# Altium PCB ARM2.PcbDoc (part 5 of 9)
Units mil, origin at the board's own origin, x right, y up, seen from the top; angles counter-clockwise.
Board outline 4700.79 x 3937.01 mil, 6 copper layers (Top Layer, GND02, ART03, ART04, PWR05, Bottom Layer); 697 components, 508 nets, 2326 pads, 1231 vias.
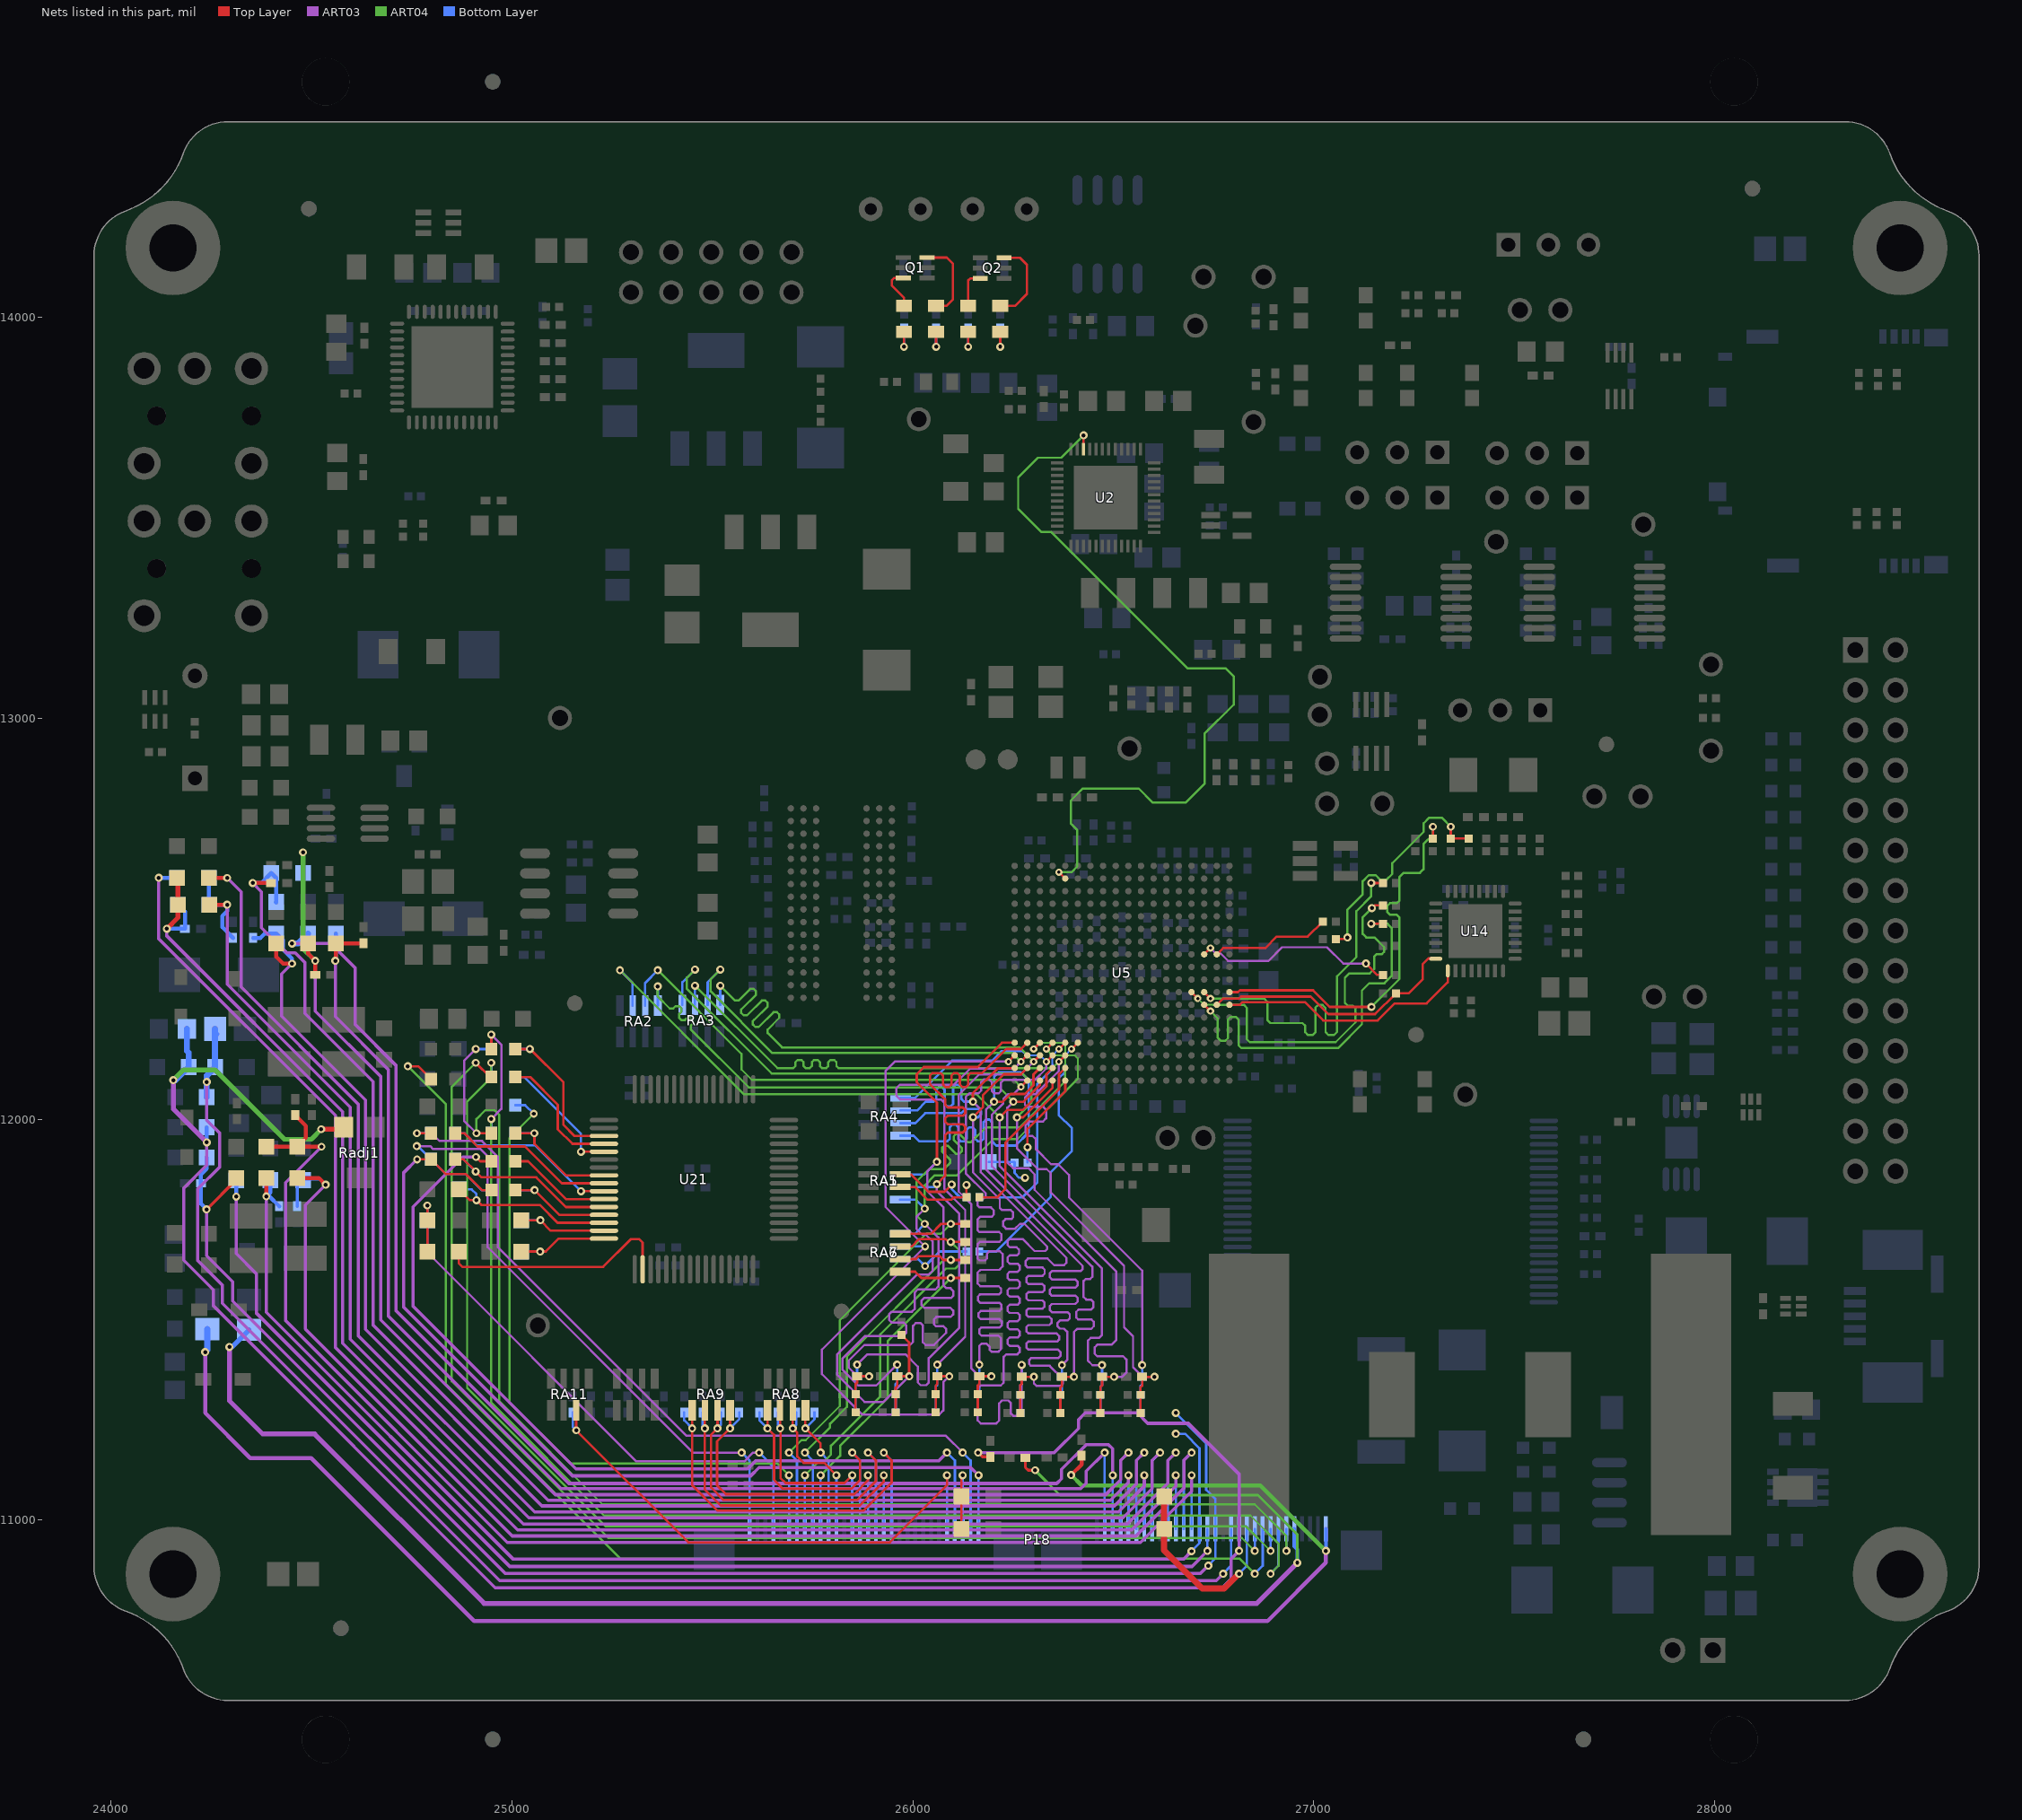
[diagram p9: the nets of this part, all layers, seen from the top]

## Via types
v1: diameter 20, hole 10, Top Layer to Bottom Layer, tented both sides, 871 vias
v2: diameter 18, hole 8, Top Layer to Bottom Layer, tented both sides, 273 vias
v3: diameter 22, hole 10, Top Layer to Bottom Layer, tented both sides, 64 vias
v4: diameter 20, hole 10, Top Layer to Bottom Layer, 18 vias
v5: diameter 22, hole 12, Top Layer to Bottom Layer, 4 vias
v6: diameter 39.37, hole 19.68, Top Layer to Bottom Layer, 1 vias

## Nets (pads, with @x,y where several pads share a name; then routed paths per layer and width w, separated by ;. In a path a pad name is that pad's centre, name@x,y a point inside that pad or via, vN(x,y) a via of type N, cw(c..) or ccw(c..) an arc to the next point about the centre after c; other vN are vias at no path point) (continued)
L_BO5: C240.1 P18.26 RA11.7 | length 1351.3
  Top Layer w6: RA11.7@25160.75,11269.25 v1(25160.75,11224.12) 25440.24,10944.62 25943,10944.62 26085.28,11086.9 v1(26085.28,11112.04)
  Bottom Layer w6: C240.1@25152.2,11268.62 25152.2,11232.66 v1(25160.75,11224.12) ; P18.26@26085.28,10978.27 v1(26085.28,11112.04)
L_CKHH: P18.4 R183.2 R187.1 R190.1 | length 1526
  Top Layer w6: R187.1@24789.63,11670 R183.2@24789.63,11748 v1(24789.63,11784.87)
  ART03 w5.5: v1(24789.63,11784.87) 24789.63,11667.99 25311,11146.62 25580,11146.62 25602,11168.62 v1(25617,11168.62)
  Bottom Layer w6: R190.1@24789.63,11748 v1(24789.63,11784.87) ; v1(25617,11168.62) 25652.21,11133.42 P18.4@25652.2,10978.27
L_CKV: R182.1 U21.5 | length 324.2
  Top Layer w6: v1(25172.64,11918.9) U21.5@25229.96,11918.9
  Bottom Layer w6: R182.1@25008.92,12105 25031,12105 25172.64,11963.36 v1(25172.64,11918.9)
L_CKVH: P18.55 R182.2 | length 3098.4
  ART04 w5.5: v1(24949.08,12140.63) 24949.08,12104.53 24888.8,12044.25 24888.8,11329.9 25234.12,10984.57 26831.03,10984.57 v1(26892.36,10923.24)
  Bottom Layer w6: R182.2@24949.08,12105 v1(24949.08,12140.63) ; v1(26892.36,10923.24) P18.55@26892.36,10978.27
L_CLK1: R187.2 U21.18 | length 590.3
  Top Layer w6: R187.2@24868.37,11670 24868.37,11640.23 24876.8,11631.8 25227.67,11631.8 25296.67,11700.8 25318.25,11700.8 25326.42,11692.63 U21.18@25326.42,11625.59
L_DIO1: P18.1 R148.2 R171.2 | length 1690.6
  ART03 w5.5: v1(24763,11933) 24796.62,11933 24804,11925.62 24922,11925.62 24940,11907.62 24940,11680.62 25451.94,11168.68 v1(25573.47,11168.68)
  Bottom Layer w6: v1(24763,11933) 24766.08,11933 R148.2@24799.08,11900 24836.08,11863 24885,11863 24925,11823 R171.2@24949.45,11823 ; v1(25573.47,11168.68) 25593.16,11148.99 P18.1@25593.16,10978.27
L_DIO2: P18.30 R166.2 R174.2 | length 2358.8
  Top Layer w6: v1(24764,11900) R166.2@24799.08,11900 24836.08,11863 24886,11863 24926,11823 R174.2@24949.45,11823
  ART03 w8: v1(24764,11900) 24730,11866 24730,11531.62 25151,11110.62 25596,11110.62 25617,11131.62 26144.43,11131.62 v1(26164.02,11112.04)
  Bottom Layer w6: P18.30@26164.02,10978.27 v1(26164.02,11112.04)
L_GO0: C226.1 P18.14 RA8.6 | length 537.1
  Top Layer w6: RA8.6@25669.25,11274.25 v1(25669.25,11229.12) 25670.21,11228.16 25670.21,11105.42 25683,11092.62 25829.64,11092.62 v1(25849.06,11112.04)
  Bottom Layer w6: C226.1@25663.47,11268.62 25663.47,11234.9 v1(25669.25,11229.12) ; P18.14@25849.06,10978.27 v1(25849.06,11112.04)
L_GO1: C227.1 P18.15 RA8.5 | length 735.9
  Top Layer w6: RA8.5@25637.76,11274.25 v1(25637.76,11229.12) 25654,11212.87 25654,11100.62 25676,11078.62 25846.75,11078.62 25868.75,11100.62 25868.75,11148.99 v1(25849.06,11168.68)
  Bottom Layer w6: C227.1@25617.71,11268.62 25617.71,11249.17 v1(25637.76,11229.12) ; v1(25849.06,11168.68) 25868.75,11148.99 P18.15@25868.74,10978.27
L_GO2: C228.1 P18.16 RA9.8 | length 796.4
  Top Layer w6: RA9.8@25544.49,11274.25 v1(25544.49,11229.12) 25512.12,11196.76 25512.12,11086.57 25534.08,11064.62 25854,11064.62 25888.43,11099.05 v1(25888.43,11112.04)
  Bottom Layer w6: v1(25544.49,11229.12) 25567.24,11251.87 C228.1@25567.24,11268.62 ; P18.16@25888.43,10978.27 v1(25888.43,11112.04)
L_GO3: C229.1 P18.17 RA9.7 | length 963.3
  Top Layer w6: RA9.7@25512.99,11274.25 v1(25512.99,11229.12) 25497.12,11213.25 25497.12,11081.57 25528.08,11050.62 25861,11050.62 25908.12,11097.74 25908.12,11148.99 v1(25888.43,11168.68)
  Bottom Layer w6: v1(25512.99,11229.12) 25521.48,11237.61 C229.1@25521.48,11268.62 ; v1(25888.43,11168.68) 25908.12,11148.99 P18.17@25908.11,10978.27
L_GO4: C233.1 P18.18 RA9.6 | length 876.8
  Top Layer w6: RA9.6@25481.5,11274.25 v1(25481.5,11229.12) 25481.5,11076.2 25521.08,11036.62 25868,11036.62 25927.8,11096.42 v1(25927.8,11112.04)
  Bottom Layer w6: C233.1@25475.71,11268.62 25475.71,11234.9 v1(25481.5,11229.12) ; P18.18@25927.8,10978.27 v1(25927.8,11112.04)
L_GO5: C234.1 P18.19 RA9.5 | length 1069.5
  Top Layer w6: RA9.5@25450,11274.25 v1(25450,11229.12) 25450,11086.7 25513.08,11023.62 25877,11023.62 25947.49,11094.11 25947.49,11148.99 v1(25927.8,11168.68)
  Bottom Layer w6: C234.1@25429.95,11268.62 25429.95,11249.17 v1(25450,11229.12) ; v1(25927.8,11168.68) 25947.49,11148.99 P18.19@25947.48,10978.27
L_LDH: P18.27 R177.2 | length 2213.9
  Top Layer w6: v1(24911,11905.62) 24921.62,11895 R177.2@24949.08,11895
  ART03 w8: v1(24911,11905.62) 24878,11905.62 24754,11781.62 24754,11533.62 25160,11127.62 25588,11127.62 25608,11147.62 26064.22,11147.62 v1(26085.28,11168.68)
  Bottom Layer w6: v1(26085.28,11168.68) 26104.97,11148.99 P18.27@26104.96,10978.27
L_OE: R180.1 U21.4 | length 325.7
  Top Layer w6: R180.1@25008.92,12105 25046,12105 25115,12036 25115,11975 25151.42,11938.58 U21.4@25229.96,11938.58
L_OEH: P18.53 R180.2 | length 3105.3
  Top Layer w6: v1(24910.45,12140.63) 24946.08,12105 R180.2@24949.08,12105
  ART04 w5.5: v1(24910.45,12140.63) 24850.62,12080.8 24850.62,11346.08 25241.12,10955.57 26820.66,10955.57 v1(26852.99,10923.24)
  Bottom Layer w6: v1(26852.99,10923.24) P18.53@26852.99,10978.27
L_POL: R188.1 U21.10 | length 430.9
  Top Layer w6: v1(25172.64,11820.47) U21.10@25229.96,11820.47
  Bottom Layer w6: R188.1@24858.92,11965 24882,11965 24912,11935 25058.11,11935 v1(25172.64,11820.47)
L_POLH: P18.29 R185.2 R188.2 | length 2092.7
  Top Layer w6: v1(24763.45,11965) R185.2@24799.08,11965
  ART03 w5.5: v1(24763.45,11965) 24800.62,11965 24820,11945.62 24926,11945.62 24965,11906.62 24965,11681.62 25436.05,11210.57 26082.75,11210.57 v1(26124.65,11168.68)
  Bottom Layer w6: v1(24763.45,11965) R188.2@24799.08,11965 ; v1(26124.65,11168.68) 26144.34,11148.99 P18.29@26144.33,10978.27
L_REV: P18.28 R146.2 R169.1 | length 268.8
  Top Layer w6: R146.2@26121.65,10978.27 R169.1@26121.65,11059.16 26121.65,11109.04 v1(26124.65,11112.04)
  Bottom Layer w6: P18.28@26124.65,10978.27 v1(26124.65,11112.04)
L_RLB: P18.6 R197.2 | length 1706.6
  ART04 w5.5: v1(25055,12013.62) 24994.12,11952.75 24994.12,11293.57 25146.12,11141.57 25662.04,11141.57 v1(25691.58,11112.04)
  Bottom Layer w6: R197.2@25008.92,12035 25033.62,12035 v1(25055,12013.62) ; P18.6@25691.58,10978.27 v1(25691.58,11112.04)
L_RO0: C220.1 P18.7 RA7.8 | length 1136.5
  Top Layer w6: RA7.8@25968.37,11714.24 26046.24,11714.24 26071,11739 v1(26095,11739) C220.1@26131,11739
  ART04 w5.5: v1(25691.58,11168.68) 25722.52,11199.62 25733,11199.62 25818,11284.62 25818,11498.62 26033.62,11714.24 26070.24,11714.24 v1(26095,11739)
  Bottom Layer w6: v1(25691.58,11168.68) 25711.27,11148.99 P18.7@25711.26,10978.27
L_RO1: C221.1 P18.8 RA7.7 | length 1080
  Top Layer w6: RA7.7@25968.37,11682.75 25997.75,11682.75 26016,11701 26082,11701 26089,11694 v1(26095,11694) C221.1@26131,11694
  ART04 w5.5: v1(25730.95,11112.04) 25765.53,11146.62 25779,11146.62 25796,11163.62 25796,11185.62 25919,11308.62 25919,11463.62 26083,11627.62 26106,11627.62 26118,11639.62 26118,11671 v1(26095,11694)
  Bottom Layer w6: P18.8@25730.95,10978.27 v1(25730.95,11112.04)
L_RO2: C222.1 P18.9 RA7.6 | length 1009.7
  Top Layer w6: RA7.6@25968.37,11651.25 26008.25,11651.25 26015.62,11658.62 26066.87,11658.62 26076.5,11649 v1(26095,11649) C222.1@26131,11649
  ART04 w5.5: v1(25730.95,11168.68) 25794,11231.73 25794,11240.62 25836,11282.62 25836,11407.62 26077.38,11649 v1(26095,11649)
  Bottom Layer w6: v1(25730.95,11168.68) 25750.64,11148.99 P18.9@25750.63,10978.27
L_RO3: C223.1 P18.10 RA7.5 | length 929.4
  Top Layer w6: RA7.5@25968.37,11619.76 26006,11619.76 26021.76,11604 v1(26095,11604) C223.1@26131,11604
  ART04 w5.5: v1(25770.32,11112.04) 25819,11160.72 25819,11185.62 25938,11304.62 25938,11447 v1(26095,11604)
  Bottom Layer w6: P18.10@25770.32,10978.27 v1(25770.32,11112.04)
L_RO4: C224.1 P18.11 RA8.8 | length 368.8
  Top Layer w6: RA8.8@25732.24,11274.25 v1(25732.24,11229.12) 25770.32,11191.05 v1(25770.32,11168.68)
  Bottom Layer w6: v1(25732.24,11229.12) 25755,11251.87 C224.1@25755,11268.62 ; v1(25770.32,11168.68) 25790.01,11148.99 P18.11@25790,10978.27
L_RO5: C225.1 P18.12 RA8.7 | length 414.1
  Top Layer w6: RA8.7@25700.75,11274.25 v1(25700.75,11229.12) 25712,11217.87 25712,11158.62 25728,11142.62 25779.1,11142.62 v1(25809.69,11112.04)
  Bottom Layer w6: v1(25700.75,11229.12) 25709.24,11237.61 C225.1@25709.24,11268.62 ; P18.12@25809.69,10978.27 v1(25809.69,11112.04)
L_SEL0: R204.2 R208.1 U21.16 | length 267.6
  Top Layer w6: R204.2@25023.37,11670 v1(25071,11670) 25085,11670 25117.36,11702.36 U21.16@25229.96,11702.36
  Bottom Layer w6: R208.1@25023.37,11670 v1(25071,11670)
L_SEL1: R205.2 R209.1 U21.15 | length 264.6
  Top Layer w6: R205.2@25023.74,11748 v1(25071.37,11748) 25097.32,11722.05 U21.15@25229.96,11722.05
  Bottom Layer w6: R209.1@25023.74,11748 v1(25071.37,11748)
L_SEL2: R206.2 R210.1 U21.14 | length 459.7
  Top Layer w6: R206.2@24868.37,11825 24895.37,11798 v1(24912,11798) 24924,11786 25070,11786 25114.27,11741.73 U21.14@25229.96,11741.73
  Bottom Layer w6: R210.1@24868.37,11825 24900,11825 24912,11813 v1(24912,11798)
L_SPOL: R185.1 U21.9 | length 422.7
  Top Layer w6: R185.1@24858.92,11965 24882,11965 24915,11932 25033,11932 25124.84,11840.16 U21.9@25229.96,11840.16
L_STB: R177.1 U21.11 | length 260.1
  Top Layer w6: R177.1@25008.92,11895 25041,11895 25135.21,11800.79 U21.11@25229.96,11800.79
L_STH1: R148.1 R166.1 U21.12 | length 484.1
  Top Layer w6: R166.1@24858.92,11900 24880,11900 v1@24910,11870 ; v1@24909.81,11869.81 v1(24910,11869.62) 24924.62,11855 25061,11855 25134.9,11781.1 U21.12@25229.96,11781.1
  Bottom Layer w6: R148.1@24858.92,11900 24879.62,11900 v1(24910,11869.62)
L_STH2: R171.1 R174.1 U21.13 | length 291.9
  Top Layer w6: R174.1@25009.29,11823 v1@25055,11823 ; v1(25056.92,11823) 25118.5,11761.42 U21.13@25229.96,11761.42
  Bottom Layer w6: R171.1@25009.29,11823 v1(25056.92,11823)
L_STV1: R179.1 R181.1 U21.8 | length 327.8
  Top Layer w6: R181.1@25008.92,11965 v1(25056.55,11965) 25056.55,11938.45 25135.16,11859.84 U21.8@25229.96,11859.84
  Bottom Layer w6: R179.1@25008.92,11965 v1(25056.55,11965)
L_STV2: R184.1 R186.1 U21.3 | length 409
  Top Layer w6: R184.1@25008.92,12175 v1(25045,12175) 25046,12175 25129,12092 25129,11986 25156.73,11958.27 U21.3@25229.96,11958.27
  Bottom Layer w6: R186.1@25008.92,12175 v1(25045,12175)
L_STVDH: P18.57 R181.2 R186.2 | length 3325.6
  Top Layer w6: v1(24912,11965) R181.2@24949.08,11965
  ART03 w5.5: v1(24910.45,12175) 24881,12145.55 24881,11996 v1(24912,11965)
  ART04 w5.5: v1(24912,11965) 24912,12000.45 24934.12,12022.57 24957.12,12022.57 24969.12,12010.57 24969.12,11296.57 25226.2,11039.5 26852.81,11039.5 26931.73,10960.57 v1(26931.73,10923.24)
  Bottom Layer w6: v1(24910.45,12175) R186.2@24949.08,12175 ; v1(26931.73,10923.24) P18.57@26931.73,10978.27
L_STVUH: P18.56 R179.2 R184.2 | length 3321.9
  Top Layer w6: R184.2@24949.08,12175 v1(24949.08,12210.92)
  ART03 w5.5: v1(24949.08,12000.63) 24974,12025.55 24974,12186 v1(24949.08,12210.92)
  ART04 w5.5: v1(24949.08,12000.63) 24949.08,11292.62 25230.12,11011.57 26842.12,11011.57 26912.05,10941.65 26912.05,10886.29 v1(26892.36,10866.6)
  Bottom Layer w6: R179.2@24949.08,11965 v1(24949.08,12000.63) ; v1(26892.36,10866.6) 26912.05,10886.29 P18.56@26912.05,10978.27
L_UDB: P18.54 R196.2 | length 3236.3
  Top Layer w6: v1(24741,12132) 24767.08,12132 R196.2@24799.08,12100
  ART04 w5.5: v1(24741,12132) 24835.12,12037.88 24835.12,11339.57 25270.12,10904.57 26815.01,10904.57 v1(26852.99,10866.6)
  Bottom Layer w6: v1(26852.99,10866.6) 26872.68,10886.29 P18.54@26872.68,10978.27
L_V1: C264.1 P18.34 R224.2 R225.1 | length 3331.9
  Top Layer w10: v1(24560,12395) 24561,12396 R225.1@24561,12438 24629,12438 C264.1@24630,12439
  ART03 w8: v1(24560,12395) 24560,12255.7 24692,12123.7 24692,11509.62 25123,11078.62 26419,11078.62 26432.61,11092.24 26432.61,11122.01 v1@26478.97,11168.37
  Bottom Layer w6: v1(26478.66,11168.68) 26478.66,10978.58 P18.34@26478.98,10978.27
  Bottom Layer w10: v1(24560,12395) 24561,12396 R224.2@24561,12463
L_V2: P18.35 R218.2 | length 3353.7
  ART03 w8: v1(24451.91,12438) 24548.7,12438 24609.12,12377.57 24609.12,12236.57 24711,12134.7 24711,11522.62 25142,11091.62 26359,11091.62 26371,11103.62 26371,11126.62 26433,11188.62 26488,11188.62 26498.66,11177.96 v1(26498.66,11112.04)
  Bottom Layer w6: P18.35@26498.66,10978.27 v1(26498.66,11112.04)
  Bottom Layer w15: v1(24451.91,12438) 24466.91,12438 R218.2@24491.91,12463
L_V3: C266.1 P18.36 R226.2 R227.1 | length 3699
  Top Layer w10: R226.2@24491.91,12438 24491.91,12413.09 v1(24510,12395) C266.1@24510,12360
  ART03 w8: v1(24510,12395) 24510,12269.7 24673,12106.7 24673,11499.62 25109,11063.62 26481,11063.62 26518.34,11100.96 26518.34,11148.99 v1(26538.03,11168.68)
  ART04 w12: v1(24479.37,12665.52) 24479.37,12425.63 v1(24510,12395)
  Bottom Layer w6: P18.36@26518.35,10978.27 26518.34,11148.99 v1(26538.03,11168.68)
  Bottom Layer w10: R227.1@24479.37,12614 v1(24479.37,12665.52)
L_V4: C267.1 P18.37 R227.2 R228.1 | length 3655.2
  Top Layer w10: v1(24354.11,12589) C267.1@24400,12589
  ART03 w8: v1(24354.11,12589) 24376.06,12567.06 24376.06,12477.69 24438.74,12415 24460,12415 24484.12,12390.88 24484.12,12263.57 24654,12093.7 24654,11486.62 25091,11049.62 26493,11049.62 26538.03,11094.65 v1(26538.03,11112.04)
  Bottom Layer w6: P18.37@26538.03,10978.27 v1(26538.03,11112.04)
  Bottom Layer w10: v1(24354.11,12589) 24375.63,12589 R227.2@24400.63,12614 24412.81,12601.81 R228.1@24412.81,12541.74 ; R228.1@24411.94,12540.87 R228.1@24412.81,12540
L_V5: C268.1 P18.38 R228.2 R229.1 | length 3654.9
  Top Layer w10: R229.1@24412.81,12438 24412.81,12405.18 24430,12388 v1(24451.91,12388)
  ART03 w7: 24426.12,12362.22 v1(24451.91,12388)
  ART03 w8: 24426.12,12362.22 24426.12,12256.88 24635,12048 24635,11475.62 25075,11035.62 26503,11035.62 26557.71,11090.33 26557.71,11148.99 v1(26577.4,11168.68)
  Bottom Layer w6: P18.38@26557.72,10978.27 26557.71,11148.99 v1(26577.4,11168.68)
  Bottom Layer w10: C268.1@24355,12452 24373,12452 24384,12463 R228.2@24412.81,12463 24429.06,12446.75 24429.06,12423.61 24451.91,12400.77 v1(24451.91,12388)
L_V6: P18.39 R221.2 | length 3652.3
  Top Layer w6: v1@24290.06,12602 v1(24290.33,12601.72)
  Top Layer w10: R221.2@24244.72,12602 v1@24290.06,12602
  ART03 w8: v1(24290.33,12601.72) 24325.07,12566.99 24325.07,12329.93 24617,12038 24617,11460.62 25057,11020.62 26513,11020.62 26577.4,11085.02 v1(26577.4,11112.04)
  Bottom Layer w6: P18.39@26577.4,10978.27 v1(26577.4,11112.04)
L_V7: C270.1 P18.40 R222.1 R230.2 R231.1 | length 3978.1
  Top Layer w10: R231.1@24246.3,12535 v1(24290.33,12535)
  ART03 w8: v1(24290.33,12535) 24290.33,12336.36 24597,12029.7 24597,11451.62 25043,11005.62 26524,11005.62 26597.08,11078.7 26597.08,11148.99 v1(26616.77,11168.68)
  Bottom Layer w6: P18.40@26597.09,10978.27 26597.08,11148.99 v1(26616.77,11168.68)
  Bottom Layer w10: R230.2@24244.72,12602 24244.72,12535 R222.1@24246.3,12535 v1(24290.33,12535) 24290.33,12519.33 24278,12507 24278,12479 C270.1@24305,12452
L_V8: C271.1 P18.42 R222.2 R231.2 R232.1 | length 4037.7
  Top Layer w6: R232.1@24166.26,12601.37 R232.1@24165.63,12602 R232.1@24167.56,12600.07
  Top Layer w12: v1(24140,12475) 24167.56,12502.56 R231.2@24167.56,12535 R232.1@24167.56,12600.07
  ART03 w8: v1(24140,12475) 24140,12456.7 24578,12018.7 24578,11441.62 25029,10990.62 26535,10990.62 26636.45,11092.07 26636.45,11148.99 v1(26656.14,11168.68)
  Bottom Layer w6: P18.42@26636.46,10978.27 26636.45,11148.99 v1(26656.14,11168.68)
  Bottom Layer w10: v1(24140,12475) C271.1@24185,12475 24185,12517.56 R222.2@24167.56,12535
L_V9: P18.43 R219.2 | length 3889.9
  ART03 w8: v1(24119.74,12602) 24119.74,12449.96 24560,12009.7 24560,11430.62 25015,10975.62 26546,10975.62 26656.14,11085.76 v1(26656.14,11112.04)
  Bottom Layer w6: P18.43@26656.14,10978.27 v1(26656.14,11112.04)
  Bottom Layer w10: v1(24119.74,12602) R219.2@24165.63,12602
L_V10: C273.1 P18.44 R233.2 R234.1 | length 3345.1
  Top Layer w10: R234.1@24465,11853 24519.4,11853 v1(24535.8,11836.6)
  ART03 w8: v1(24535.8,11836.6) 24485,11785.8 24485,11476.62 25001,10960.62 26557,10960.62 26676,11079.62 26676,11149.17 v1(26695.51,11168.68)
  Bottom Layer w6: P18.44@26675.83,10978.27 26675.82,11148.99 v1(26695.51,11168.68)
  Bottom Layer w8: C273.1@24465,11783 24465,11838 24477.5,11850.5 24521.9,11850.5 v1(24535.8,11836.6)
L_V11: C274.1 P18.45 R234.2 R235.1 | length 3421.9
  Top Layer w10: R235.1@24388,11931.74 R234.2@24465,11931.74 ; C274.1@24460,12010 24487,11983 24487,11953.74 R234.2@24465,11931.74 ; v1@24525.33,11931.74 R234.2@24465,11931.74
  ART03 w8: v1(24525.61,11931.46) 24436,11841.85 24436,11497.62 24989,10944.62 26568,10944.62 26695.51,11072.13 v1(26695.51,11112.04)
  Bottom Layer w6: P18.45@26695.51,10978.27 v1(26695.51,11112.04)
L_V12: C275.1 P18.46 R235.2 R236.1 | length 3326
  Top Layer w10: v1@24388,11812.67 R235.2@24388,11853
  ART03 w8: v1(24388,11807.37) 24388,11518.62 25004,10902.62 26675,10902.62 v1(26695,10922.62)
  Bottom Layer w6: v1(26656,11215.36) 26679,11215.36 26715.2,11179.17 P18.46@26715.2,10978.27 26715.2,10942.82 v1(26695,10922.62)
  Bottom Layer w8: v1(24388,11807.37) v1@24388.37,11807
  Bottom Layer w10: R236.1@24398,11848 24398,11817.37 v1(24388,11807.37) 24395.63,11807.37 C275.1@24420,11783
L_V13: P18.47 R220.1 | length 3061.5
  ART03 w8: v1@24312.72,11807 24312.72,11664.9 24363,11614.62 24363,11516.62 24995,10884.62 26696.27,10884.62 v1(26734.88,10923.24)
  Bottom Layer w6: v1(26734.88,10923.24) P18.47@26734.88,10978.27
  Bottom Layer w10: v1(24313,11807) R220.1@24313,11847.63 R220.1@24313,11852.63
L_V14: C277.1 P18.48 R237.2 R238.1 | length 3696.9
  Top Layer w8: v1(24239,11775.08) 24313,11849.08 R237.2@24313,11852.63
  ART03 w8: v1(24239,11775.08) 24239,11659.62 24304,11594.62 24304,11546.62 24983,10867.62 26718,10867.62 v1(26737,10886.62)
  Bottom Layer w6: v1(26656,11267.36) 26732,11191.36 26732,11075.62 26754.57,11053.06 P18.48@26754.57,10978.27 26754.57,10904.19 v1(26737,10886.62)
  Bottom Layer w10: 24225,11799.37 C277.1@24225,11840 ; v1(24239,11775.08) 24225,11789.08 C277.1@24225,11840 ; R238.1@24239.37,11905 24239.37,11876.37 24225,11862 C277.1@24225,11840
L_VCOM: C206.2 C207.1 P18.51 R172.2 R178.1 Radj1.2 | length 5322.9
  Top Layer w8: v1(26163,11168.62) 26173.67,11157.95 C207.1@26193.28,11157.95
  Top Layer w12: v1(24525,11975) 24575.67,11975 Radj1.2@24580.63,11979.96
  ART03 w8: v1(24239.37,11942.13) 24239.37,11885.37 24182,11828 24182,11648.62 24256,11574.62 24256,11534.62 24959,10831.62 26772,10831.62 26794,10853.62 26794,10903.62 v1(26813.62,10923.24) 26813.62,11115.08 26687.12,11241.57 26586.12,11241.57 26560.12,11267.57 26430.12,11267.57 26413.12,11250.57 26413.12,11228.57 26353.17,11168.62 v1(26163,11168.62)
  ART03 w12: v1(24156,12097.5) 24156,12025.5 v1(24239.37,11942.13)
  ART04 w12: v1(24156,12097.5) 24181.5,12123 24260,12123 24433,11950 24500,11950 v1(24525,11975)
  Bottom Layer w7: v1(26813.62,10923.24) P18.51@26813.62,10978.27
  Bottom Layer w10: v1(24239.37,11942.13) R172.2@24239.37,11980
  Bottom Layer w15: v1(24156,12097.5) 24161.87,12097.5 R178.1@24194.37,12130 24194.37,12165.63 24190,12170 C206.2@24190,12225
L_VGH: C231.1 FB14.2 P18.58 | length 4044.8
  Top Layer w7: C231.1@26281,11155.62 26281,11131.62 26288,11124.62 v1(26305,11124.62)
  ART03 w12: v1(24296,11432) 24296,11298 24379,11215 24508.62,11215 24931,10792.62 26858,10792.62 v1(26959,10893.62)
  ART04 w7: v1(26305,11124.62) 26367.05,11062.57 26861.12,11062.57 26959,10964.7 v1(26959,10893.62)
  Bottom Layer w9: P18.58@26951.42,10978.27 26951.42,10935.2 26959,10927.62 v1(26959,10893.62)
  Bottom Layer w12: v1(24296,11432) 24302.4,11432 FB14.2@24345,11474.6
L_VGL: C232.1 FB16.2 P18.62 | length 4137.8
  Top Layer w10: v1(26395,11112.62) 26421,11138.62 C232.1@26421,11160.62
  ART03 w10: v1(24235.63,11419) 24235.63,11267.37 24348,11155 24500,11155 24906.38,10748.62 26885,10748.62 27030.15,10893.77 v1(27030.15,10923.24)
  ART04 w10: v1(26395,11112.62) 26421.05,11086.57 26866.82,11086.57 v1(27030.15,10923.24)
  Bottom Layer w9: v1(27030.15,10923.24) P18.62@27030.16,10978.27
  Bottom Layer w15: v1(24235.63,11419) 24241,11424.37 FB16.2@24241,11476.6
L_VLC: FB15.2 P18.50 R162.1 R223.1 | length 3704.6
  ART03 w8: v1(24239.37,12093) 24239.37,11997.63 24272,11965 24272,11881 24217,11826 24217,11647.62 24278.5,11586.12 24278.5,11541.12 24970,10849.62 26757.28,10849.62 v1(26774.25,10866.6)
  Bottom Layer w6: v1(26774.25,10866.6) 26793.94,10886.29 P18.50@26793.94,10978.27
  Bottom Layer w10: FB15.2@24264.37,12210.39 FB15.2@24266.4,12212.42
  Bottom Layer w15: R162.1@24239.37,12055 v1(24239.37,12093) 24239.37,12108.74 R223.1@24260.63,12130 24260,12130.63 FB15.2@24260,12225
L_XON: P18.52 R147.2 R170.1 | length 495.7
  Top Layer w15: R170.1@26626.82,11059.16 R147.2@26626.82,10978.27 26626.82,10924.88 26722.12,10829.57 26776.59,10829.57 v1(26813.62,10866.6)
  Bottom Layer w6: v1(26813.62,10866.6) 26833.31,10886.29 P18.52@26833.31,10978.27
LCD_DATA0: C173.1 R70.2 R95.1 RA5.2 U5.R1 | length 1861.8
  Top Layer w6: R70.2@25857.33,11268.94 R95.1@25857.33,11313.94 25857.33,11338.94 25861.19,11342.8 C173.1@25861.19,11358.94 v1(25891.19,11358.94) ; v1(26060.26,11893.74) 26060.26,12041.74 26010,12092 26010,12112.46 26027.54,12130 26162,12130 26222.77,12190.77 U5.R1@26254.26,12190.77
  ART03 w5.5: v1(25891.19,11358.94) 25861.99,11358.94 25840,11380.93 25840,11397.62 25879.09,11436.71 25992.87,11436.71 26000.72,11444.56 26000.72,11484.72 26007.19,11491.19 26019.93,11491.19 26025.33,11485.79 26025.33,11443.49 26032.1,11436.71 26052.67,11436.71 26082.9,11466.94 26082.9,11477.25 26076.69,11483.46 26058.19,11483.46 26053.17,11488.48 26053.17,11501.12 26058.89,11506.84 26094.61,11506.84 26101.05,11513.28 26101.05,11522.59 26093.87,11529.77 26028.49,11529.77 26021.93,11536.34 26021.93,11547.75 26028.18,11554 26095.66,11554 26101.05,11559.39 26101.05,11571.4 26094.04,11578.41 26084.04,11578.41 26077,11585.45 26077,11779.62 26035.9,11820.72 26035.9,11869.39 v1(26060.26,11893.74)
  Bottom Layer w6: RA5.2@25968.37,11862.25 26028.76,11862.25 v1(26060.26,11893.74)
LCD_DATA1: C171.1 R69.2 R94.1 RA5.3 U5.R2 | length 1864.7
  Top Layer w6: v1(26060,11838) 26081,11859 26081,11960.2 26087.3,11966.5 26124.7,11966.5 26131,11972.8 26131,11981.2 26124.7,11987.5 26087.3,11987.5 26081,11993.8 26081,12002.2 26087.3,12008.5 26124.7,12008.5 26131,12014.8 26131,12023.2 26124.7,12029.5 26087.3,12029.5 26081,12035.8 26081,12050 26043,12088 26043,12109 26049,12115 26069.2,12115 26075.5,12108.7 26075.5,12086.3 26081.8,12080 26090.2,12080 26096.5,12086.3 26096.5,12108.7 26102.8,12115 26111.2,12115 26117.5,12108.7 26117.5,12086.3 26123.8,12080 26132.2,12080 26138.5,12086.3 26138.5,12108.7 26144.8,12115 26173,12115 26233,12175 26269.99,12175 U5.R2@26285.76,12190.77
  ART03 w5.5: v1(25861.19,11387.94) 25886.78,11413.53 25982.13,11413.53 26012.81,11382.84 26012.81,11343.44 26019.57,11336.69 26033.44,11336.69 26039.96,11343.21 26039.96,11404.16 26116,11480.2 26116,11764 26060,11820 v1(26060,11838)
  Bottom Layer w6: R69.2@25857.33,11268.94 R94.1@25857.33,11313.94 25857.33,11355.08 C171.1@25861.19,11358.94 v1(25861.19,11387.94) ; RA5.3@25968.37,11830.75 26052.75,11830.75 v1(26060,11838)
LCD_DATA2: C172.1 R68.2 R75.1 R93.1 RA5.4 U5.R3 | length 1867
  Top Layer w6: R68.2@25957.33,11268.94 R93.1@25957.33,11313.94 25957.33,11331.08 25961.19,11334.94 C172.1@25961.19,11358.94 v1(25991.19,11358.94) 25991.19,11443.29 R75.1@25972,11462.48 ; v2(26301.51,12175.03) U5.R3@26317.26,12190.77
  ART03 w5.5: v1(25991.19,11358.94) 25927.22,11294.97 25879.72,11294.97 25811,11363.68 25811,11412.74 26010.88,11612.62 26040,11612.62 26050,11622.62 26050,11694.62 26033,11711.62 26024,11711.62 26009,11726.62 26009,11756 v1(26030,11777)
  ART04 w4.4: v2(26301.51,12175.03) 26317.01,12190.53 26375,12190.53 26380,12185.52 26380,12165 26385.47,12159.53 26403.97,12159.53 26411.49,12152 26411.49,12136.59
  ART04 w5.5: v1(26030,11777) 26030,11835 26055,11860 26110.91,11860 26201.27,11950.36 26261.18,11950.36 26411.74,12100.92 26411.74,12136.59
  Bottom Layer w6: RA5.4@25968.37,11799.26 26007.74,11799.26 v1(26030,11777)
LCD_DATA3: C170.1 R67.2 R92.1 RA6.1 U5.R4 | length 1866.2
  Top Layer w6: v2(26333,12175.03) U5.R4@26348.75,12190.77
  ART03 w5.5: v1(25961.19,11387.94) 25908.87,11335.62 25864.11,11335.62 25825,11374.73 25825,11403.62 25881,11459.62 25976.63,11459.62 25983.79,11466.79 25983.79,11486.24 25976.77,11493.26 25947.3,11493.26 25941.03,11499.53 25941.03,11513.11 25947.68,11519.77 25997.89,11519.77 26004.56,11526.44 26004.56,11567.4 26012.61,11575.45 26056.98,11575.45 26064,11582.47 26064,11705 v1(26030,11739)
  ART04 w4.4: v2(26333,12175.03) 26348.99,12159.04 26370.92,12159.04 26380,12149.96 26380,12136.34
  ART04 w5.5: v1(26030,11739) 26009.5,11759.5 26009.5,11844.5 26040.5,11875.5 26078,11875.5 26093.15,11890.65 26093.15,11899.35 26072.95,11919.55 26072.95,11928.24 26078.75,11934.04 26087.45,11934.04 26107.64,11913.84 26116.34,11913.84 26122.14,11919.64 26122.14,11928.34 26101.94,11948.54 26101.94,11957.24 26107.74,11963.03 26116.44,11963.03 26136.64,11942.83 26145.33,11942.83 26181.94,11979.44 26265.61,11979.44 26380,12093.83 26380,12136.34
  Bottom Layer w6: R67.2@25957.33,11268.94 R92.1@25957.33,11313.94 25957.33,11340.08 25961.19,11343.94 C170.1@25961.19,11358.94 v1(25961.19,11387.94) ; RA6.1@25968.37,11714.24 26005.24,11714.24 v1(26030,11739)
LCD_DATA4: C169.1 R66.2 R91.1 RA6.2 U5.T1 | length 1866
  Top Layer w6: R66.2@26057.33,11268.94 R91.1@26057.33,11313.94 26057.33,11335.94 26061.19,11339.8 C169.1@26061.19,11358.94 v1(26091.19,11358.94) ; v2(26238.51,12143.54) U5.T1@26254.26,12159.28
  ART03 w5.5: v1(26091.19,11358.94) 26076.31,11344.07 26076.31,11273.67 26066.43,11263.78 25873.78,11263.78 25773.26,11364.29 25773.26,11425.26 v1(26030.75,11682.75) 25932,11781.5 25932,12120 25955.54,12143.54 v2(26238.51,12143.54)
  Bottom Layer w6: RA6.2@25968.37,11682.75 v1(26030.75,11682.75)
LCD_DATA5: C163.1 R65.2 R90.1 RA3.3 U5.T2 | length 2342.4
  Top Layer w6: v2(26270.01,12143.54) U5.T2@26285.76,12159.28
  ART03 w5.5: v1(26061.19,11387.94) 26130.89,11457.64 26130.89,11773.73 26079,11825.62 26079,12040.62 26070.27,12049.35 25968.27,12049.35 25958.64,12058.98 25958.64,12076.88 25968.09,12086.33 26103.33,12086.33 26143,12126 26252.48,12126 v2(26270.01,12143.54)
  ART04 w5.5: v1(25520,12373) 25496,12349 25496,12319 25650,12165 26248.55,12165 v2(26270.01,12143.54)
  Bottom Layer w6: RA3.3@25488.5,12285 25488.5,12341.5 v1(25520,12373) ; R65.2@26057.33,11268.94 R90.1@26057.33,11313.94 26057.33,11333.08 26061.19,11336.94 C163.1@26061.19,11358.94 v1(26061.19,11387.94)
LCD_DATA6: C162.1 R64.2 R89.1 RA3.4 U5.T3 | length 2346.5
  Top Layer w6: R64.2@26162.33,11268.94 R89.1@26162.33,11313.94 26162.33,11335.94 26166.19,11339.8 C162.1@26166.19,11358.94 v1(26196.19,11358.94) ; v2(26301.51,12143.54) U5.T3@26317.26,12159.28
  ART03 w5.5: v1(26196.19,11358.94) 26166,11358.94 26145.79,11379.15 26145.79,11788.59 26114.75,11819.62 26114.75,12060.58 26166.03,12111.85 26269.83,12111.85 v2(26301.51,12143.54)
  ART04 w5.5: v1(25520,12333) 25557.02,12295.98 25565.72,12295.98 25594.7,12324.96 25603.4,12324.96 25609.2,12319.16 25609.2,12310.47 25575.87,12277.13 25572.44,12273.7 25572.44,12265.01 25578.23,12259.21 25586.93,12259.21 25590.36,12262.64 25623.69,12295.97 25632.39,12295.97 25638.19,12290.17 25638.19,12281.48 25604.86,12248.14 25601.43,12244.71 25601.43,12236.02 25607.23,12230.22 25615.92,12230.22 25652.69,12266.98 25661.38,12266.98 25667.18,12261.18 25667.18,12252.48 25638.2,12223.5 25638.2,12214.8 25674,12179 26266.05,12179 v2(26301.51,12143.54)
  Bottom Layer w6: RA3.4@25520,12285 v1(25520,12333)
LCD_DATA7: C161.1 R63.2 R88.1 RA4.1 U5.T4 | length 2336.3
  Top Layer w6: v2(26333,12143.54) U5.T4@26348.75,12159.28
  ART03 w5.5: v1(26166.19,11387.94) 26166.19,11434.72 26171.31,11439.85 26184.6,11439.85 26191.75,11432.7 26191.75,11425.29 26196.78,11420.26 26213.97,11420.26 26219.91,11426.21 26219.91,11453.83 26213.4,11460.35 26171.31,11460.35 26166.19,11465.47 26166.19,11475.72 26171.31,11480.85 26216.74,11480.85 26221.75,11485.86 26221.75,11495.93 26216.33,11501.35 26169.57,11501.35 26164.03,11506.88 26164.03,11515.93 26169.96,11521.85 26216.18,11521.85 26221.27,11526.93 26221.27,11536.66 26215.58,11542.35 26168.08,11542.35 26162.7,11547.73 26162.7,11557.78 26167.77,11562.85 26215.18,11562.85 26220.38,11568.05 26220.38,11577.22 26214.26,11583.35 26168.76,11583.35 26161.69,11590.42 26161.69,11617.21 26168.72,11624.24 26215.6,11624.24 26223.94,11632.58 26223.94,11663.97 26217.28,11670.64 26191.27,11670.64 26185.11,11664.47 26185.11,11652.79 26180.03,11647.72 26166.43,11647.72 26161.36,11652.79 26161.36,11687.96 26167.58,11694.18 26216.23,11694.18 26220.93,11698.89 26220.93,11713.14 26215.49,11718.58 26166.21,11718.58 26161.36,11723.43 26161.36,11749.94 26168.08,11756.66 26196.52,11756.66 26201.94,11762.09 26201.94,11773.02 26194.99,11779.97 26166.83,11779.97 26161.36,11785.44 26161.36,11796.33 26167.71,11802.69 26177.45,11802.69 26182.08,11807.32 26182.08,11814.92 26132.32,11864.68 26132.32,12055.53 26141.08,12064.28 26163.63,12064.28 26170.52,12071.18 26170.52,12092.19 26177.58,12099.26 26190.34,12099.26 26197.13,12092.46 26197.13,12070.77 26203.61,12064.28 26214.15,12064.28 26220.36,12070.49 26220.36,12091.52 26226.69,12097.84 26304.76,12097.84 26333,12126.09 v2(26333,12143.54)
  Bottom Layer w4.4: 26273,12170 26283.47,12159.53 26317.01,12159.53 v2(26333,12143.54)
  Bottom Layer w6: RA4.1@25969.37,12053.24 26005.24,12053.24 26098,12146 26198,12146 26222,12170 26273,12170 ; R63.2@26162.33,11268.94 R88.1@26162.33,11313.94 26166.19,11317.8 C161.1@26166.19,11358.94 v1(26166.19,11387.94)
LCD_DATA8: C160.1 R62.2 R87.1 RA4.2 U5.U1 | length 2335.8
  Top Layer w6: v1(26150.07,12043.76) 26150.07,12065.07 26212.24,12127.24 26253.71,12127.24 U5.U1@26254.26,12127.78 ; R62.2@26268.23,11267.56 R87.1@26268.23,11312.56 26268.23,11336.56 26272.09,11340.42 C160.1@26272.09,11357.56 v1(26302.09,11357.56)
  ART03 w5.5: v1(26150.07,12043.76) 26170,12023.83 26170,11867.62 26383.29,11654.33 26383.29,11641.79 26377.48,11635.98 26352.56,11635.98 26336.24,11652.3 26287.44,11652.3 26281.72,11646.58 26281.72,11635.08 26286.7,11630.11 26323.63,11630.11 26328.92,11624.82 26328.92,11614.83 26323.7,11609.61 26288.61,11609.61 26283.48,11604.48 26283.48,11594.23 26288.61,11589.11 26323.2,11589.11 26328.11,11584.2 26328.11,11573.43 26323.29,11568.61 26288.61,11568.61 26283.48,11563.48 26283.48,11553.23 26288.61,11548.11 26323.49,11548.11 26328.88,11542.72 26328.88,11532.74 26323.74,11527.61 26288.61,11527.61 26283.48,11522.48 26283.48,11512.23 26288.61,11507.11 26340.84,11507.11 26346.03,11501.91 26346.03,11491.97 26340.66,11486.61 26288.61,11486.61 26283.48,11481.48 26283.48,11471.23 26288.61,11466.11 26357.99,11466.11 26364.93,11459.17 26364.93,11450.44 26360.1,11445.61 26288.61,11445.61 26283.48,11440.48 26283.48,11430.23 26288.61,11425.11 26362.44,11425.11 26368.24,11419.31 26368.24,11409.58 26363.27,11404.61 26295.75,11404.61 26290.62,11399.48 26290.62,11389.23 26294.68,11385.17 26341.65,11385.17 26374.58,11352.24 26374.58,11340.68 26369.35,11335.44 26308.15,11335.44 26302.09,11341.5 v1(26302.09,11357.56)
  Bottom Layer w6: RA4.2@25969.37,12021.75 26010.75,12021.75 26032.76,12043.76 26052.2,12043.76 26058.5,12050.06 26058.5,12073.43 26064.8,12079.73 26073.2,12079.73 26079.5,12073.43 26079.5,12038.06 26085.8,12031.76 26094.2,12031.76 26100.5,12038.06 26100.5,12079.28 26106.8,12085.58 26115.2,12085.58 26121.5,12079.28 26121.5,12050.06 26127.8,12043.76 v1(26150.07,12043.76)
LCD_DATA9: C157.1 R61.2 R86.1 RA4.3 U5.U2 | length 2341.8
  Top Layer w6: v1(26150.07,12004.76) 26175,12029.68 26175,12060 26227.02,12112.02 26270,12112.02 U5.U2@26285.76,12127.78
  ART03 w5.5: v1(26150.07,12004.76) 26150.07,11867.55 26217.1,11800.52 26217.1,11778.86 26222.77,11773.2 26244.42,11773.2 26250.46,11767.16 26250.46,11755.7 26245.87,11751.11 26231.56,11751.11 26225.65,11745.2 26225.65,11733.59 26232.42,11726.82 26255.54,11726.82 26267.64,11738.92 26278.49,11738.92 26335.22,11682.19 26335.22,11676.05 26330.4,11671.23 26303.83,11671.23 26273.72,11701.33 26241.79,11701.33 26236.67,11696.21 26236.67,11685.96 26241.79,11680.83 26258.6,11680.83 26265.19,11674.24 26265.19,11665.51 26260.02,11660.33 26241.79,11660.33 26236.67,11655.21 26236.67,11644.96 26241.79,11639.83 26261.54,11639.83 26266.67,11634.71 26266.67,11624.46 26261.54,11619.33 26241.79,11619.33 26236.67,11614.21 26236.67,11603.96 26241.79,11598.83 26261.54,11598.83 26266.67,11593.71 26266.67,11583.46 26261.54,11578.33 26241.79,11578.33 26236.67,11573.21 26236.67,11562.96 26241.79,11557.83 26261.54,11557.83 26266.67,11552.71 26266.67,11542.46 26261.54,11537.33 26241.79,11537.33 26236.67,11532.21 26236.67,11521.96 26241.79,11516.83 26261.54,11516.83 26266.67,11511.71 26266.67,11501.46 26261.54,11496.33 26241.79,11496.33 26236.67,11491.21 26236.67,11480.96 26241.79,11475.83 26261.54,11475.83 26266.67,11470.71 26266.67,11460.46 26261.54,11455.33 26241.79,11455.33 26236.67,11450.21 26236.67,11439.96 26241.79,11434.83 26261.54,11434.83 26266.67,11429.71 26266.67,11419.24 26261.11,11413.68 26233.24,11413.68 26226.92,11407.36 26226.92,11343.08 26219.85,11336.01 26170.04,11336.01 26161.9,11327.87 26161.9,11248.89 26169.43,11241.36 26208.48,11241.36 26215.48,11248.36 26215.48,11291.11 26222.97,11298.6 26237.93,11298.6 26244.85,11291.68 26244.85,11265.86 26250.47,11260.23 26266.68,11260.23 26271.41,11264.96 v1(26271.41,11387.24)
  Bottom Layer w6: RA4.3@25969.37,11990.25 26006.25,11990.25 26031,12015 26121,12015 26131.76,12025.76 26164.24,12025.76 26170,12020 26170,12012 26162.76,12004.76 v1(26150.07,12004.76) ; R61.2@26268.23,11267.56 R86.1@26268.23,11312.56 26268.23,11335.7 26272.09,11339.56 C157.1@26272.09,11357.56 26272.09,11386.56 v1(26271.41,11387.24)
LCD_DATA10: C156.1 R60.2 R85.1 RA4.4 U5.U3 | length 2321.9
  Top Layer w6: v1(26203,12043.62) 26224.43,12043.62 ; 26224.51,12043.54 26243.98,12063 26279.38,12063 26301.06,12084.68 26301.06,12111.58 U5.U3@26317.26,12127.78
  ART03 w5.5: v1(26203,12043.62) 26182.8,12023.42 26182.8,11874.82 26423.85,11633.78 26423.85,11626.22 26418.78,11621.15 26347.21,11621.15 26342.09,11616.03 26342.09,11605.78 26347.21,11600.65 26405.18,11600.65 26410.84,11595 26410.84,11585.1 26405.9,11580.15 26347.21,11580.15 26342.09,11575.03 26342.09,11564.78 26347.21,11559.65 26406.06,11559.65 26411.54,11554.17 26411.54,11545.25 26405.45,11539.15 26347.21,11539.15 26342.09,11534.03 26342.09,11523.78 26347.21,11518.65 26386.46,11518.65 26391.59,11513.53 26391.59,11503.28 26386.46,11498.15 26367.13,11498.15 26361,11492.03 26361,11483.24 26366.58,11477.65 26377.31,11477.65 26385.09,11469.88 26385.09,11399.56 v1(26372.09,11386.56)
  Bottom Layer w6: RA4.4@25969.37,11958.76 26002.24,11958.76 26016,11945 26086.2,11945 26092.5,11951.3 26092.5,11980.37 26098.8,11986.67 26107.2,11986.67 26113.5,11980.37 26113.5,11951.3 26119.8,11945 26128.2,11945 26134.5,11951.3 26134.5,11973.4 26140.8,11979.7 26149.2,11979.7 26155.5,11973.4 26155.5,11951.3 26161.8,11945 26170.2,11945 26176.5,11951.3 26176.5,11992.62 26182.8,11998.92 26191.2,11998.92 26197.5,11992.62 26197.5,11945.06 26208.33,11934.22 26256.22,11934.22 26289.23,11967.23 26289.23,12097.94 26270.18,12117 26214.97,12117 26203,12105.03 v1(26203,12043.62) ; R60.2@26368.23,11267.56 R85.1@26368.23,11312.56 26372.09,11316.42 C156.1@26372.09,11357.56 v1(26372.09,11386.56)
LCD_DATA11: C168.1 R59.2 R84.1 RA2.2 U5.U4 | length 2300.7
  Top Layer w6: v1(26216.98,12004.54) 26235.45,12023 26274.38,12023 26333.39,12082.01 26333.39,12112.42 U5.U4@26348.75,12127.78
  ART03 w5.5: v1(26216.98,12004.54) 26216.98,11882.91 26472.09,11627.81 26472.09,11462.16 26464.5,11454.57 26443.63,11454.57 26436.74,11447.68 26436.74,11397.9 26448.08,11386.56 v1(26472.09,11386.56)
  ART04 w5.5: v1(25269.76,12371.37) 25579.13,12062 26159.52,12062 v1(26216.98,12004.54)
  Bottom Layer w6: v1(25269.76,12371.37) 25301.25,12339.87 RA2.2@25301.25,12283.37 ; R59.2@26468.23,11267.56 R84.1@26468.23,11312.56 26468.23,11332.7 26472.09,11336.56 C168.1@26472.09,11357.56 v1(26472.09,11386.56)
LCD_DATA12: C167.1 R58.2 R83.1 RA2.3 U5.V2 | length 2305.3
  Top Layer w6: v2(26270.01,12080.54) U5.V2@26285.76,12096.28 ; R58.2@26368.23,11267.56 R83.1@26368.23,11312.56 26368.23,11330.7 26372.09,11334.56 C167.1@26372.09,11357.56 v1(26402.09,11357.56)
  ART03 w5.5: v2(26270.01,12080.54) 26252.15,12062.67 26238.05,12062.67 26226,12050.62 26226,12039.62 26197.5,12011.12 26197.5,11882.5 26447.74,11632.26 26447.74,11606.96 26442.04,11601.26 26430.95,11601.26 26426.12,11596.43 26426.12,11556.66 26432.61,11550.17 26444.17,11550.17 26450.73,11543.61 26450.73,11531.29 26445.04,11525.6 26414.01,11525.6 26407.95,11519.53 26407.95,11505.42 26412.77,11500.6 26445.66,11500.6 26451.57,11494.69 26451.57,11483.67 26444.84,11476.94 26409.87,11476.94 26402.09,11469.16 v1(26402.09,11357.56)
  ART04 w5.5: v1(25364.24,12371.37) 25573,12162.61 25573,12124 25598.75,12098.25 26252.3,12098.25 v2(26270.01,12080.54)
  Bottom Layer w6: RA2.3@25332.75,12283.37 25332.75,12339.87 v1(25364.24,12371.37)
LCD_DATA13: C166.1 R57.2 R82.1 RA2.4 U5.V3 | length 2304.3
  Top Layer w6: v1(26251,12043.62) 26276,12043.62 26317.26,12084.88 U5.V3@26317.26,12096.28 ; R57.2@26468.23,11267.56 R82.1@26468.23,11312.56 26468.23,11331.7 26472.09,11335.56 C166.1@26472.09,11357.56 v1(26502.09,11357.56)
  ART03 w5.5: v1(26251,12043.62) 26236,12028.62 26236,11891.96 26250.06,11877.91 26288.36,11877.91 26303.75,11862.51 26303.75,11823.87 26507.06,11620.56 26507.06,11448.78 26496.49,11438.2 26460.92,11438.2 26453.77,11431.05 26453.77,11415.29 26460.24,11408.81 26524.66,11408.81 26532.88,11400.58 26532.88,11368.18 26522.27,11357.56 v1(26502.09,11357.56)
  ART04 w5.5: v1(25364.24,12331.37) 25364.24,12305.88 25393.96,12276.16 25402.66,12276.16 25408.62,12282.13 25417.32,12282.13 25423.12,12276.33 25423.12,12267.63 25417.16,12261.67 25417.16,12252.97 25422.95,12247.17 25431.65,12247.17 25437.61,12253.14 25446.31,12253.14 25452.11,12247.34 25452.11,12238.64 25446.15,12232.68 25446.15,12223.98 25591.13,12079 26215.62,12079 v1(26251,12043.62)
  Bottom Layer w6: RA2.4@25364.24,12283.37 v1(25364.24,12331.37)
LCD_DATA14: C165.1 R56.2 R81.1 RA3.1 U5.V4 | length 2294.3
  Top Layer w6: v1(26260,12004.62) 26275.17,12004.62 26348.75,12078.2 U5.V4@26348.75,12096.28 ; R56.2@26568.23,11267.56 R81.1@26568.23,11312.56 26568.23,11331.7 26572.09,11335.56 C165.1@26572.09,11357.56 v1(26603.09,11357.56)
  ART03 w5.5: v1(26260,12004.62) 26260,11927.39 26311.81,11875.58 26334.04,11875.58 26344,11865.62 26344,11817.62 26527.02,11634.6 26527.02,11481.23 26549.42,11458.84 26549.42,11381.17 26573.03,11357.56 v1(26603.09,11357.56)
  ART04 w5.5: v1(25457.01,12373) 25437,12352.99 25437,12325 25648,12114 26273,12114 26296,12091 26296,12040.62 v1(26260,12004.62)
  Bottom Layer w6: RA3.1@25425.51,12285 25425.51,12341.5 v1(25457.01,12373)
LCD_DATA15: C164.1 R55.2 R80.1 RA3.2 U5.T5 | length 2300.2
  Top Layer w6: v2(26364.5,12143.54) U5.T5@26380.25,12159.28
  ART03 w5.5: v2(26364.5,12143.54) 26364.5,12120.56 26305.85,12061.91 26287.4,12061.91 26279.69,12054.2 26279.69,12036.2 26285.17,12030.73 26325.92,12030.73 26332.67,12023.98 26332.67,12002.06 26324.93,11994.32 26290.79,11994.32 26281.57,11985.09 26281.57,11966.57 26289.85,11958.28 26298.72,11958.28 26307.35,11949.65 26307.35,11925.19 26344.65,11887.89 26362.78,11887.89 26390,11860.67 26390,11804.62 26572.09,11622.54 v1(26572.09,11386.56)
  ART04 w5.5: v1(25457.01,12333) 25662.52,12127.49 25702.12,12127.49 25707.25,12132.61 25707.25,12142.36 25712.38,12147.49 25722.62,12147.49 25727.75,12142.36 25727.75,12132.61 25732.88,12127.49 25743.12,12127.49 25748.25,12132.61 25748.25,12142.36 25753.38,12147.49 25763.62,12147.49 25768.75,12142.36 25768.75,12132.61 25773.88,12127.49 25784.12,12127.49 25789.25,12132.61 25789.25,12142.36 25794.38,12147.49 25804.62,12147.49 25809.75,12142.36 25809.75,12132.61 25814.88,12127.49 26348.45,12127.49 v2(26364.5,12143.54)
  Bottom Layer w6: RA3.2@25457.01,12285 v1(25457.01,12333) ; R55.2@26568.23,11267.56 R80.1@26568.23,11312.56 26568.23,11334.56 26572.09,11338.42 C164.1@26572.09,11357.56 v1(26572.09,11386.56)
LCD_DE: R48.2 RA6.3 | length 187.8
  Bottom Layer w6: RA6.3@25968.37,11651.25 26013.25,11651.25 v1(26030.75,11633.75) 26067,11670 R48.2@26133.86,11670
LCD_HSYNC: R47.2 RA1.3 | length 210.6
  Top Layer w6: RA1.3@25968.37,11862.25 25995.75,11862.25 26039,11819 26079,11819 v1(26097,11837)
  Bottom Layer w6: v1(26097,11837) 26097,11826 26118,11805 R47.2@26133.86,11805
LCD_PCLK: R45.2 R111.2 | length 134.2
  ART04 w5.5: v1(26280,11854) v1@26286,11854
  Bottom Layer w6: R111.2@26189.37,11893.19 26252.67,11893.19 R45.2@26253.86,11892 26253.86,11865.76 26265.62,11854 v1(26280,11854) v1@26286,11854
LCD_VSYNC: R46.2 RA1.2 | length 213.2
  Top Layer w6: RA1.2@25968.37,11830.75 26005.25,11830.75 26036.88,11799.12 26095.84,11799.12 26101.72,11805 R46.2@26133.86,11805 v1@26133.86,11837.14
  other v1: 26134,11836
LCDDE: R48.1 U5.R6 | length 674.7
  Top Layer w6: v2(26395.99,12175.03) U5.R6@26411.74,12190.77
  Bottom Layer w4.4: 26380,12135.98 26380,12159.04 v2(26395.99,12175.03)
  Bottom Layer w6: R48.1@26166.14,11670 26208,11670 26344,11806 26344,11867.46 26397,11920.46 26397,11977.47 26364,12010.47 26364,12102 26380,12118 26380,12135.98 26380.25,12136.23
LCDPCLK: R45.1 U5.V5 | length 243.3
  Top Layer w6: v1(26286.14,11929.86) 26286.14,11975.59 26380.25,12069.7 U5.V5@26380.25,12096.28
  Bottom Layer w6: R45.1@26286.14,11892 v1(26286.14,11929.86)
LCDVHYNC: R47.1 U5.R5 | length 537.1
  Top Layer w6: v2(26364.5,12175.03) U5.R5@26380.25,12190.77
  Bottom Layer w4.4: 26348.5,12135.99 26348.5,12159.03 v2(26364.5,12175.03)
  Bottom Layer w6: R47.1@26166.14,11805 26273,11805 26310.64,11842.64 26310.64,12088.13 26348.51,12126 26348.51,12135.99
LCDVSYNC: R46.1 U5.U5 | length 437.2
  Top Layer w6: R46.1@26166.14,11805 26210,11805 26231,11826 26231,11940.45 26364.89,12074.34 26364.89,12112.42 U5.U5@26380.25,12127.78
LDO_PGOOD: U2.46 U5.B5 | length 1951.9
  Top Layer w6: v2(26364.5,12615.97) U5.B5@26380.25,12600.22 ; U2.46@26425.94,13671.06 v1(26425.94,13705.57)
  ART04 w5.5: v2(26364.5,12615.97) 26396,12615.97 26409.67,12629.64 26409.67,12722.03 26394.12,12737.57 26394.12,12794.2 26424.5,12824.57 26563.35,12824.57 26597.89,12790.03 26681.48,12790.03 26727.61,12836.16 26727.61,12961.06 26800.12,13033.57 26800.12,13104.57 26780.12,13124.57 26685.12,13124.57 26345.02,13464.67 26320.15,13464.67 26262.94,13521.89 26262.94,13600.8 26311.87,13649.72 26370.08,13649.72 v1(26425.94,13705.57)
LEDAA: D2.2 R72.2 | length 85.4
  Top Layer w6: v1(25978.19,13926.22) D2.2@25978.19,13963.22
  Bottom Layer w6: v1(25978.19,13926.22) R72.2@25978.19,13974.57
LEDAC: D2.1 Q1.6 | length 107.4
  Top Layer w6: Q1.6@25976.67,14097.63 25953.18,14097.63 25948.12,14092.57 25948.12,14078.57 25978.19,14048.5 D2.1@25978.19,14028.22
LEDBA: D3.2 R73.2 | length 85.4
  Top Layer w6: v1(26058.19,13926.22) D3.2@26058.19,13963.22
  Bottom Layer w6: v1(26058.19,13926.22) R73.2@26058.19,13974.57
LEDBC: D3.1 Q1.3 | length 208.6
  Top Layer w6: Q1.3@26035.72,14148.81 26084.6,14148.81 26100.19,14133.22 26100.19,14044.22 26084.19,14028.22 D3.1@26058.19,14028.22
LEDCA: D4.2 R74.2 | length 85.4
  Top Layer w6: v1(26138.19,13926.22) D4.2@26138.19,13963.22
  Bottom Layer w6: v1(26138.19,13926.22) R74.2@26138.19,13974.57
LEDCC: D4.1 Q2.6 | length 95.9
  Top Layer w6: D4.1@26138.19,14028.22 26138.19,14091.22 26143.97,14097 Q2.6@26168.67,14097
LEDDA: D5.2 R71.2 | length 85.4
  Top Layer w6: v1(26218.19,13926.22) D5.2@26218.19,13963.22
  Bottom Layer w6: v1(26218.19,13926.22) R71.2@26218.19,13974.57
LEDDC: D5.1 Q2.3 | length 216.2
  Top Layer w6: D5.1@26218.19,14028.22 26255.19,14028.22 26284.79,14057.82 26284.79,14131.02 26267.63,14148.18 Q2.3@26227.72,14148.18
MDIO_CLK: U5.M18 U14.17 | length 645.3
  Top Layer w6: U5.M18@26789.7,12285.26 26816,12285.26 26822.74,12292 26978,12292 27024,12246 27159.55,12246 27202.12,12288.57 27281.57,12288.57 27334.16,12341.16 U14.17@27334.16,12370 U14.17@27334.16,12359.24
MDIO_DATA: R119.2 U5.M17 U14.16 | length 652.4
  Top Layer w6: U5.M17@26758.2,12285.26 26773.94,12301 26814,12301 26818.76,12305.76 26992.24,12305.76 27036,12262 27153,12262 R119.2@27205,12314 27237,12314 27272,12349 27272,12387 27286,12401 U14.16@27304.11,12401
MII1_COL: R138.1 U5.H16 | length 508.5
  Top Layer w6: U5.H16@26726.7,12411.24 v2(26742.45,12426.99) ; v1(27130.18,12388.24) 27158.59,12359.83 R138.1@27172.72,12359.83
  ART03 w5.5: v2(26742.45,12426.99) 26753.43,12416 26765.38,12416 26786.6,12394.78 26887.21,12394.78 26921.22,12428.79 27033.21,12428.79 27073.76,12388.24 v1(27130.18,12388.24)
MII1_CRS_DV: R139.1 U5.H17 | length 298.4
  Top Layer w6: U5.H17@26758.2,12411.24 26773.94,12426.98 26879.36,12426.98 26907.76,12455.38 26985.1,12455.38 R139.1@27022.72,12493
MII1_REFCLK: R28.2 R124.1 R140.1 | length 586.9
  Top Layer w6: R28.2@27055,12449.24 v1@27080.24,12449.24 ; v1(27341.68,12729.32) R124.1@27341.68,12700.14 R140.1@27385.97,12700.14
  ART04 w5.5: v1(27084,12453) 27084,12522.45 27122.12,12560.57 27122.12,12593.41 27137.42,12608.7 27154.15,12608.7 27165.12,12597.73 27181.94,12597.73 27195.99,12611.79 27195.99,12638.58 27274,12716.59 27274,12738 27288,12752 27319,12752 v1(27341.68,12729.32)
MII1_RXCLK: R131.1 U5.L18 | length 984.3
  Top Layer w6: U5.L18@26789.7,12316.76 26811,12316.76 26815.74,12321.5 26998.5,12321.5 27040,12280 v1(27144,12280) ; R131.1@27297.4,12700.14 v1(27297.4,12729.32)
  ART04 w5.5: v1(27144,12280) 27213.82,12349.82 27213.82,12502.37 27205.98,12510.21 27189.74,12510.21 27182.97,12516.98 27182.97,12531.75 27190.04,12538.82 27207.11,12538.82 27213.82,12545.52 27213.82,12604.08 27224.14,12614.4 27264.62,12614.4 27273.51,12623.29 27273.51,12685.96 27297.4,12709.84 v1(27297.4,12729.32)
MII1_RXD0: R128.1 U5.M16 | length 983.1
  Top Layer w6: U5.M16@26726.7,12285.26 v2(26742.45,12269.52) ; v1(27143.54,12487.33) R128.1@27172.72,12487.33
  ART04 w5.5: v2(26742.45,12269.52) 26760.66,12251.3 26760.66,12203.19 26768.82,12195.02 26778.9,12195.02 26786.05,12202.18 26786.05,12248.41 26792.87,12255.23 26806.01,12255.23 26812.6,12248.64 26812.6,12184.23 26819.68,12177.15 27060.5,12177.15 27120.12,12236.78 27120.12,12320.73 27138.53,12339.13 27176.37,12339.13 27194.28,12357.04 27194.28,12477.04 27183.98,12487.33 v1(27143.54,12487.33)
MII1_RXD1: R127.1 U5.L15 | length 980.9
  Top Layer w6: U5.L15@26695.21,12316.76 v2(26710.96,12301.02) ; v1(27145.12,12526.57) 27151.72,12533.17 R127.1@27172.72,12533.17
  ART04 w4.4: v2(26710.96,12301.02) 26726.46,12285.52 26748.87,12285.52
  ART04 w5.5: 26749.39,12285.27 26825.45,12285.27 26833.03,12277.68 26833.03,12199.8 26840.72,12192.12 27054.53,12192.12 27103.78,12241.37 27103.78,12276.5 27097.41,12282.87 27085.15,12282.87 27077.59,12290.43 27077.59,12352.56 27088.63,12363.6 27139.65,12363.6 27150.47,12374.42 27150.47,12405.5 27156.21,12411.24 27169.56,12411.24 27175.34,12417.02 27175.34,12429.35 27151.57,12453.11 27131.16,12453.11 27122.12,12462.14 27122.12,12503.57 v1(27145.12,12526.57)
MII1_RXD2: R126.1 U5.L16 | length 984.8
  Top Layer w6: U5.L16@26726.7,12316.76 v2(26742.45,12301.02) ; v1(27143.54,12589) R126.1@27172.72,12589
  ART04 w5.5: v2(26742.45,12301.02) 26875.99,12301.02 26884.08,12292.93 26884.08,12247.16 26891.56,12239.68 26971.89,12239.68 26978.98,12232.59 26978.98,12216.77 26986.04,12209.72 26997.39,12209.72 27004.15,12216.48 27004.15,12278.42 27010.48,12284.76 27021.77,12284.76 27029.45,12277.08 27029.45,12216.91 27036.64,12209.72 27050.29,12209.72 27058.01,12217.44 27058.01,12356.42 27106.12,12404.53 27106.12,12518.57 27143.54,12555.99 v1(27143.54,12589)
